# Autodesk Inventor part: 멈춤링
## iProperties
IsCustomPart: 0
Created: 2009-02
Part Number: 멈춤링
Material: 강, 연강
Description: 리테이닝 링(C형)
Document SubType Name: Modeling
Standard: KS B 1336
Designer: KYOUNG IL JANG
Standards Organization: KS
Language: ko-KR
Size Designation: 22 x 1.2
Categories: <MemberInstance><Categories><Category DisplayName="샤프트 부품" InternalName="7f7aeb1f-a693-4053-b835-cee3144e0d98" Mnemonic="SHFT"><Category DisplayName="써클립" Inter
Density: 1 g/cm^3
Author: KYOUNG IL JANG
